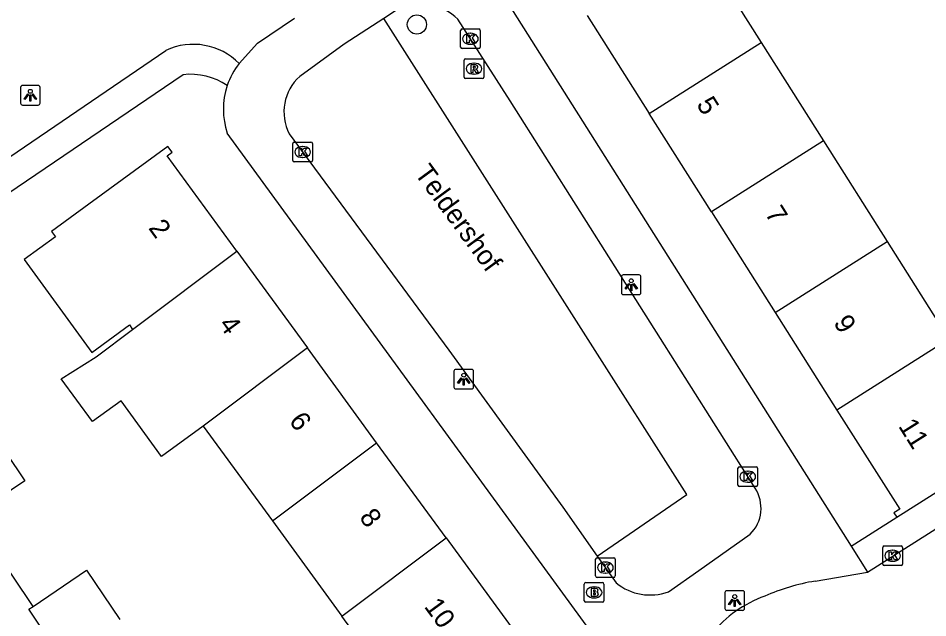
# Model space of a CAD drawing. Extents: x 157466 to 158888, y 383063 to 384677.
# Drawn here: x 158057.81 to 158104.15, y 383566.64 to 383597.18 of the extents above; entities that cross this region are included whole.
import ezdxf

# ---------------------------------------------------------------- set-up
doc = ezdxf.new("R2010")
doc.units = 0
for name, color, linetype in [('IMGEO_Boom', 7, 'Continuous'), ('IMGEO_Brandkraan', 7, 'Continuous'), ('IMGEO_Groenvoorziening', 7, 'Continuous'), ('IMGEO_Kolk', 7, 'Continuous'), ('IMGEO_Lichtpunt', 7, 'Continuous'), ('IMGEO_Openbare_ruimte_label', 7, 'Continuous'), ('IMGEO_Pand', 7, 'Continuous'), ('IMGEO_Pand_nummerreeks', 7, 'Continuous'), ('IMGEO_Rijbaan_lokaal_open', 7, 'Continuous'), ('IMGEO_Rioolput', 7, 'Continuous'), ('IMGEO_Voetpad_open', 7, 'Continuous')]:
    doc.layers.add(name, color=color, linetype=linetype)

msp = doc.modelspace()

# ---------------------------------------------------------------- linework, layer by layer
at = {"layer": 'IMGEO_Boom'}
msp.add_circle((158078.119, 383596.855), 0.489, dxfattribs=at)
at = {"layer": 'IMGEO_Brandkraan'}
for p, q in [((158086.649, 383567.512), (158086.649, 383568.364)), ((158086.724, 383568.438), (158087.576, 383568.438)), ((158087.65, 383568.364), (158087.65, 383567.512)), ((158087.137, 383568.218), (158087.162, 383568.218)), ((158087.576, 383567.438), (158086.724, 383567.438)), ((158087.16, 383567.658), (158087.135, 383567.658))]:
    msp.add_line(p, q, dxfattribs=at)
for points in [[(158086.649, 383567.512), (158086.649, 383568.364)], [(158086.724, 383568.438), (158087.576, 383568.438)], [(158087.65, 383568.364), (158087.65, 383567.512)], [(158086.997, 383568.138), (158086.997, 383567.738), (158087.21, 383567.738)], [(158087.228, 383568.138), (158086.997, 383568.138)], [(158087.176, 383568.057), (158087.122, 383568.057), (158087.122, 383567.981)], [(158087.122, 383567.981), (158087.175, 383567.981)], [(158087.184, 383567.905), (158087.122, 383567.905), (158087.122, 383567.824)], [(158087.576, 383567.438), (158086.724, 383567.438)], [(158087.122, 383567.824), (158087.184, 383567.824)]]:
    msp.add_lwpolyline(points, dxfattribs=at)
for centre, radius, start, end in [((158086.726, 383568.362), 0.0765, 91.552, 178.448), ((158086.726, 383568.362), 0.0765, 91.552, 178.448), ((158087.574, 383568.362), 0.0765, 1.552, 88.448), ((158087.574, 383568.362), 0.0765, 1.552, 88.448), ((158087.177, 383568.019), 0.0379, 267.8285, 90.9355), ((158087.185, 383567.864), 0.0404, 269.8759, 90.5077), ((158087.232, 383567.993), 0.145, 59.4692, 91.5367), ((158087.257, 383568.04), 0.0922, 285.5137, 58.1501), ((158087.262, 383567.848), 0.105, 301.3115, 78.989), ((158086.726, 383567.514), 0.0765, 181.552, 268.448), ((158086.726, 383567.514), 0.0765, 181.552, 268.448), ((158087.216, 383567.989), 0.251, 268.6676, 293.5347), ((158087.574, 383567.514), 0.0765, 271.552, 358.448), ((158087.574, 383567.514), 0.0765, 271.552, 358.448)]:
    msp.add_arc(centre, radius, start, end, dxfattribs=at)
for centre, major_axis, ratio, start_param, end_param in [((158087.136, 383567.938), (-0.387, 0.002), 0.722429, 4.712389, 7.853982), ((158087.161, 383567.938), (-0.39, 0.002), 0.717154, 1.570796, 4.712389)]:
    msp.add_ellipse(centre, major_axis=major_axis, ratio=ratio, start_param=start_param, end_param=end_param, dxfattribs=at)
at = {"layer": 'IMGEO_Groenvoorziening'}
msp.add_lwpolyline([(158087.311, 383569.79), (158091.867, 383572.916), (158076.432, 383597.167)], dxfattribs=at)
at = {"layer": 'IMGEO_Kolk'}
for p, q in [((158080.42, 383596.626), (158081.272, 383596.626)), ((158080.345, 383595.7), (158080.345, 383596.552)), ((158080.833, 383596.406), (158080.858, 383596.406)), ((158081.346, 383596.552), (158081.346, 383595.7)), ((158080.856, 383595.846), (158080.831, 383595.846)), ((158081.272, 383595.626), (158080.42, 383595.626)), ((158071.797, 383589.937), (158071.797, 383590.789)), ((158071.872, 383590.863), (158072.724, 383590.863)), ((158072.285, 383590.643), (158072.31, 383590.643)), ((158072.798, 383590.789), (158072.798, 383589.937)), ((158072.724, 383589.863), (158071.872, 383589.863)), ((158072.308, 383590.083), (158072.283, 383590.083)), ((158094.478, 383573.403), (158094.478, 383574.255)), ((158094.553, 383574.329), (158095.405, 383574.329)), ((158094.966, 383574.109), (158094.991, 383574.109)), ((158095.479, 383574.255), (158095.479, 383573.403)), ((158094.989, 383573.549), (158094.964, 383573.549)), ((158095.405, 383573.329), (158094.553, 383573.329)), ((158101.86, 383569.376), (158101.86, 383570.228)), ((158101.935, 383570.302), (158102.787, 383570.302)), ((158102.861, 383570.228), (158102.861, 383569.376)), ((158102.348, 383570.082), (158102.373, 383570.082)), ((158087.224, 383568.773), (158087.224, 383569.625)), ((158087.299, 383569.699), (158088.151, 383569.699)), ((158087.712, 383569.479), (158087.737, 383569.479)), ((158088.225, 383569.625), (158088.225, 383568.773)), ((158102.787, 383569.302), (158101.935, 383569.302)), ((158102.371, 383569.522), (158102.346, 383569.522)), ((158087.735, 383568.919), (158087.71, 383568.919)), ((158088.151, 383568.699), (158087.299, 383568.699))]:
    msp.add_line(p, q, dxfattribs=at)
for points in [[(158080.42, 383596.626), (158081.272, 383596.626)], [(158080.345, 383595.7), (158080.345, 383596.552)], [(158080.666, 383596.326), (158080.789, 383596.326), (158080.789, 383596.175), (158080.919, 383596.326), (158081.083, 383596.326), (158080.937, 383596.175), (158081.09, 383595.926), (158080.938, 383595.926), (158080.853, 383596.09), (158080.789, 383596.023), (158080.789, 383595.926), (158080.666, 383595.926), (158080.666, 383596.326)], [(158081.346, 383596.552), (158081.346, 383595.7)], [(158081.272, 383595.626), (158080.42, 383595.626)], [(158071.797, 383589.937), (158071.797, 383590.789)], [(158071.872, 383590.863), (158072.724, 383590.863)], [(158072.798, 383590.789), (158072.798, 383589.937)], [(158072.118, 383590.563), (158072.241, 383590.563), (158072.241, 383590.412), (158072.371, 383590.563), (158072.535, 383590.563), (158072.389, 383590.412), (158072.542, 383590.163), (158072.39, 383590.163), (158072.305, 383590.327), (158072.241, 383590.26), (158072.241, 383590.163), (158072.118, 383590.163), (158072.118, 383590.563)], [(158072.724, 383589.863), (158071.872, 383589.863)], [(158094.478, 383573.403), (158094.478, 383574.255)], [(158094.553, 383574.329), (158095.405, 383574.329)], [(158094.799, 383574.029), (158094.922, 383574.029), (158094.922, 383573.878), (158095.052, 383574.029), (158095.216, 383574.029), (158095.07, 383573.878), (158095.223, 383573.629), (158095.071, 383573.629), (158094.986, 383573.793), (158094.922, 383573.726), (158094.922, 383573.629), (158094.799, 383573.629), (158094.799, 383574.029)], [(158095.479, 383574.255), (158095.479, 383573.403)], [(158095.405, 383573.329), (158094.553, 383573.329)], [(158101.86, 383569.376), (158101.86, 383570.228)], [(158101.935, 383570.302), (158102.787, 383570.302)], [(158102.861, 383570.228), (158102.861, 383569.376)], [(158102.181, 383570.002), (158102.304, 383570.002), (158102.304, 383569.851), (158102.434, 383570.002), (158102.598, 383570.002), (158102.452, 383569.851), (158102.605, 383569.602), (158102.453, 383569.602), (158102.368, 383569.766), (158102.304, 383569.699), (158102.304, 383569.602), (158102.181, 383569.602), (158102.181, 383570.002)], [(158087.224, 383568.773), (158087.224, 383569.625)], [(158087.299, 383569.699), (158088.151, 383569.699)], [(158087.545, 383569.399), (158087.668, 383569.399), (158087.668, 383569.248), (158087.798, 383569.399), (158087.962, 383569.399), (158087.816, 383569.248), (158087.969, 383568.999), (158087.817, 383568.999), (158087.732, 383569.163), (158087.668, 383569.096), (158087.668, 383568.999), (158087.545, 383568.999), (158087.545, 383569.399)], [(158088.225, 383569.625), (158088.225, 383568.773)], [(158102.787, 383569.302), (158101.935, 383569.302)], [(158088.151, 383568.699), (158087.299, 383568.699)]]:
    msp.add_lwpolyline(points, dxfattribs=at)
for centre, start, end in [((158080.422, 383596.55), 91.552, 178.448), ((158080.422, 383596.55), 91.552, 178.448), ((158081.27, 383596.55), 1.552, 88.448), ((158081.27, 383596.55), 1.552, 88.448), ((158080.422, 383595.702), 181.552, 268.448), ((158080.422, 383595.702), 181.552, 268.448), ((158081.27, 383595.702), 271.552, 358.448), ((158081.27, 383595.702), 271.552, 358.448), ((158071.874, 383590.787), 91.552, 178.448), ((158071.874, 383590.787), 91.552, 178.448), ((158072.722, 383590.787), 1.552, 88.448), ((158072.722, 383590.787), 1.552, 88.448), ((158071.874, 383589.939), 181.552, 268.448), ((158071.874, 383589.939), 181.552, 268.448), ((158072.722, 383589.939), 271.552, 358.448), ((158072.722, 383589.939), 271.552, 358.448), ((158094.555, 383574.253), 91.552, 178.448), ((158094.555, 383574.253), 91.552, 178.448), ((158095.403, 383574.253), 1.552, 88.448), ((158095.403, 383574.253), 1.552, 88.448), ((158094.555, 383573.405), 181.552, 268.448), ((158094.555, 383573.405), 181.552, 268.448), ((158095.403, 383573.405), 271.552, 358.448), ((158095.403, 383573.405), 271.552, 358.448), ((158101.937, 383570.226), 91.552, 178.448), ((158101.937, 383570.226), 91.552, 178.448), ((158102.785, 383570.226), 1.552, 88.448), ((158102.785, 383570.226), 1.552, 88.448), ((158087.301, 383569.623), 91.552, 178.448), ((158087.301, 383569.623), 91.552, 178.448), ((158088.149, 383569.623), 1.552, 88.448), ((158088.149, 383569.623), 1.552, 88.448), ((158101.937, 383569.378), 181.552, 268.448), ((158101.937, 383569.378), 181.552, 268.448), ((158102.785, 383569.378), 271.552, 358.448), ((158102.785, 383569.378), 271.552, 358.448), ((158087.301, 383568.775), 181.552, 268.448), ((158087.301, 383568.775), 181.552, 268.448), ((158088.149, 383568.775), 271.552, 358.448), ((158088.149, 383568.775), 271.552, 358.448)]:
    msp.add_arc(centre, 0.0765, start, end, dxfattribs=at)
for centre, major_axis, ratio, start_param, end_param in [((158080.832, 383596.126), (-0.387, 0.002), 0.722429, 4.712389, 7.853982), ((158080.857, 383596.126), (-0.39, 0.002), 0.717154, 1.570796, 4.712389), ((158072.284, 383590.363), (-0.387, 0.002), 0.722429, 4.712389, 7.853982), ((158072.309, 383590.363), (-0.39, 0.002), 0.717154, 1.570796, 4.712389), ((158094.965, 383573.829), (-0.387, 0.002), 0.722429, 4.712389, 7.853982), ((158094.99, 383573.829), (-0.39, 0.002), 0.717154, 1.570796, 4.712389), ((158102.347, 383569.802), (-0.387, 0.002), 0.722429, 4.712389, 7.853982), ((158102.372, 383569.802), (-0.39, 0.002), 0.717154, 1.570796, 4.712389), ((158087.711, 383569.199), (-0.387, 0.002), 0.722429, 4.712389, 7.853982), ((158087.736, 383569.199), (-0.39, 0.002), 0.717154, 1.570796, 4.712389)]:
    msp.add_ellipse(centre, major_axis=major_axis, ratio=ratio, start_param=start_param, end_param=end_param, dxfattribs=at)
at = {"layer": 'IMGEO_Lichtpunt'}
for p, q in [((158057.926, 383593.654), (158057.926, 383592.847)), ((158057.926, 383593.654), (158057.926, 383592.847)), ((158058.828, 383593.749), (158058.02, 383593.749)), ((158058.828, 383593.749), (158058.02, 383593.749)), ((158058.922, 383592.847), (158058.922, 383593.654)), ((158058.922, 383592.847), (158058.922, 383593.654)), ((158058.02, 383592.753), (158058.828, 383592.753)), ((158058.02, 383592.753), (158058.828, 383592.753)), ((158088.541, 383584.006), (158088.541, 383583.199)), ((158088.541, 383584.006), (158088.541, 383583.199)), ((158089.443, 383584.101), (158088.635, 383584.101)), ((158089.443, 383584.101), (158088.635, 383584.101)), ((158089.537, 383583.199), (158089.537, 383584.006)), ((158089.537, 383583.199), (158089.537, 383584.006)), ((158088.635, 383583.105), (158089.443, 383583.105)), ((158088.635, 383583.105), (158089.443, 383583.105)), ((158080.009, 383579.199), (158080.009, 383578.392)), ((158080.009, 383579.199), (158080.009, 383578.392)), ((158080.911, 383579.294), (158080.103, 383579.294)), ((158080.911, 383579.294), (158080.103, 383579.294)), ((158081.005, 383578.392), (158081.005, 383579.199)), ((158081.005, 383578.392), (158081.005, 383579.199)), ((158080.103, 383578.298), (158080.911, 383578.298)), ((158080.103, 383578.298), (158080.911, 383578.298)), ((158093.814, 383567.925), (158093.814, 383567.118)), ((158093.814, 383567.925), (158093.814, 383567.118)), ((158094.716, 383568.02), (158093.908, 383568.02)), ((158094.716, 383568.02), (158093.908, 383568.02)), ((158094.81, 383567.118), (158094.81, 383567.925)), ((158094.81, 383567.118), (158094.81, 383567.925)), ((158093.908, 383567.024), (158094.716, 383567.024)), ((158093.908, 383567.024), (158094.716, 383567.024))]:
    msp.add_line(p, q, dxfattribs=at)
for points in [[(158058.3, 383593.318), (158058.339, 383593.29), (158058.151, 383593.028), (158058.113, 383593.055), (158058.3, 383593.318)], [(158058.402, 383593.27), (158058.449, 383593.27), (158058.449, 383592.948), (158058.402, 383592.948), (158058.402, 383593.27)], [(158058.512, 383593.29), (158058.55, 383593.317), (158058.737, 383593.055), (158058.698, 383593.027), (158058.512, 383593.29)], [(158088.915, 383583.67), (158088.954, 383583.642), (158088.766, 383583.38), (158088.728, 383583.407), (158088.915, 383583.67)], [(158089.127, 383583.642), (158089.165, 383583.669), (158089.352, 383583.407), (158089.313, 383583.379), (158089.127, 383583.642)], [(158089.017, 383583.622), (158089.064, 383583.622), (158089.064, 383583.3), (158089.017, 383583.3), (158089.017, 383583.622)], [(158080.383, 383578.863), (158080.422, 383578.835), (158080.234, 383578.573), (158080.196, 383578.6), (158080.383, 383578.863)], [(158080.485, 383578.815), (158080.532, 383578.815), (158080.532, 383578.493), (158080.485, 383578.493), (158080.485, 383578.815)], [(158080.595, 383578.835), (158080.633, 383578.862), (158080.82, 383578.6), (158080.781, 383578.572), (158080.595, 383578.835)], [(158094.188, 383567.589), (158094.227, 383567.561), (158094.039, 383567.299), (158094.001, 383567.326), (158094.188, 383567.589)], [(158094.29, 383567.541), (158094.337, 383567.541), (158094.337, 383567.219), (158094.29, 383567.219), (158094.29, 383567.541)], [(158094.4, 383567.561), (158094.438, 383567.588), (158094.625, 383567.326), (158094.586, 383567.298), (158094.4, 383567.561)]]:
    msp.add_lwpolyline(points, dxfattribs=at)
for centre in [(158058.425, 383593.452), (158089.04, 383583.804), (158080.508, 383578.997), (158094.313, 383567.723)]:
    msp.add_circle(centre, 0.0994, dxfattribs=at)
for centre, start, end in [((158058.02, 383593.654), 90, 180), ((158058.02, 383593.654), 90, 180), ((158058.828, 383593.654), 0, 90), ((158058.828, 383593.654), 0, 90), ((158058.02, 383592.847), 180, 270), ((158058.02, 383592.847), 180, 270), ((158058.828, 383592.847), 270, 0), ((158058.828, 383592.847), 270, 360), ((158088.635, 383584.006), 90, 180), ((158088.635, 383584.006), 90, 180), ((158089.443, 383584.006), 0, 90), ((158089.443, 383584.006), 0, 90), ((158088.635, 383583.199), 180, 270), ((158088.635, 383583.199), 180, 270), ((158089.443, 383583.199), 270, 0), ((158089.443, 383583.199), 270, 360), ((158080.103, 383579.199), 90, 180), ((158080.103, 383579.199), 90, 180), ((158080.911, 383579.199), 0, 90), ((158080.911, 383579.199), 0, 90), ((158080.103, 383578.392), 180, 270), ((158080.103, 383578.392), 180, 270), ((158080.911, 383578.392), 270, 0), ((158080.911, 383578.392), 270, 360), ((158093.908, 383567.925), 90, 180), ((158093.908, 383567.925), 90, 180), ((158094.716, 383567.925), 0, 90), ((158094.716, 383567.925), 0, 90), ((158093.908, 383567.118), 180, 270), ((158093.908, 383567.118), 180, 270), ((158094.716, 383567.118), 270, 0), ((158094.716, 383567.118), 270, 360)]:
    msp.add_arc(centre, 0.0946, start, end, dxfattribs=at)
at = {"layer": 'IMGEO_Pand'}
for points in [[(158092.495, 383600.924), (158095.657, 383595.935)], [(158086.789, 383597.305), (158089.952, 383592.315)], [(158089.952, 383592.315), (158095.657, 383595.935)], [(158095.657, 383595.935), (158098.833, 383590.926)], [(158093.127, 383587.307), (158089.952, 383592.315)], [(158068.947, 383585.314), (158065.402, 383590.169), (158065.652, 383590.352), (158065.435, 383590.649), (158061.397, 383587.701), (158059.506, 383586.32), (158059.705, 383586.047), (158058.105, 383584.881), (158061.55, 383580.153), (158063.474, 383581.555), (158063.637, 383581.332)], [(158098.833, 383590.926), (158093.127, 383587.307)], [(158098.833, 383590.926), (158102.075, 383585.81)], [(158093.127, 383587.307), (158096.369, 383582.191)], [(158096.369, 383582.191), (158102.075, 383585.81)], [(158102.075, 383585.81), (158105.228, 383580.836)], [(158063.637, 383581.332), (158068.947, 383585.314)], [(158068.947, 383585.314), (158072.54, 383580.392)], [(158096.369, 383582.191), (158099.522, 383577.217)], [(158067.23, 383576.41), (158065.113, 383574.857), (158063.046, 383577.688), (158061.599, 383576.631), (158060.002, 383578.819), (158061.775, 383579.936), (158063.637, 383581.332)], [(158105.228, 383580.836), (158099.522, 383577.217)], [(158072.54, 383580.392), (158067.23, 383576.41)], [(158076.069, 383575.559), (158072.54, 383580.392)], [(158099.522, 383577.217), (158102.719, 383572.174), (158102.423, 383571.987), (158102.566, 383571.761)], [(158102.566, 383571.761), (158106.79, 383574.438), (158108.848, 383575.743), (158110.56, 383576.829)], [(158056.227, 383576.451), (158058.137, 383573.619), (158055.464, 383571.816)], [(158067.23, 383576.41), (158070.759, 383571.577)], [(158070.759, 383571.577), (158076.069, 383575.559)], [(158079.606, 383570.714), (158076.069, 383575.559)], [(158070.759, 383571.577), (158074.296, 383566.732)], [(158074.296, 383566.732), (158079.606, 383570.714)], [(158079.606, 383570.714), (158083.104, 383565.922)], [(158058.564, 383567.221), (158061.292, 383569.062), (158062.983, 383566.557)], [(158060.037, 383564.577), (158058.35, 383567.077), (158058.564, 383567.221)], [(158077.795, 383561.94), (158074.296, 383566.732)]]:
    msp.add_lwpolyline(points, dxfattribs=at)
at = {"layer": 'IMGEO_Rijbaan_lokaal_open'}
for points in [[(158082.083, 383599.002), (158100.243, 383570.288)], [(158077.227, 383597.687), (158076.432, 383597.167)], [(158069.065, 383594.868), (158069.99, 383595.903), (158071.886, 383597.183)], [(158076.432, 383597.167), (158074.419, 383595.851), (158072.152, 383594.213)], [(158095.348, 383573.246), (158082.874, 383592.971), (158080.205, 383597.122)], [(158089.222, 383562.881), (158068.458, 383591.321)], [(158071.618, 383591.287), (158079.743, 383580.27), (158085.554, 383572.285), (158087.311, 383569.79)], [(158101.077, 383568.969), (158104.874, 383571.383)], [(158090.932, 383567.969), (158092.488, 383569.052), (158095.097, 383570.898)], [(158100.243, 383570.288), (158101.077, 383568.969)], [(158087.311, 383569.79), (158088.275, 383568.422)], [(158098.405, 383568.512), (158101.077, 383568.969)]]:
    msp.add_lwpolyline(points, dxfattribs=at)
for centre, radius, start, end in [((158078.297, 383595.198), 2.709, 45.2439, 113.2706), ((158071.834, 383592.634), 3.558, 141.0992, 161.8511), ((158073.771, 383592.406), 2.426, 131.8554, 207.4591), ((158072.125, 383592.539), 3.864, 161.8621, 198.3746), ((158093.794, 383572.225), 1.86, 314.4851, 33.3115), ((158090, 383570.522), 2.718, 230.5986, 290.0504), ((158100.215, 383557.781), 10.883, 99.5714, 113.6958), ((158097.895, 383562.001), 6.101, 109.6718, 141.0074)]:
    msp.add_arc(centre, radius, start, end, dxfattribs=at)
at = {"layer": 'IMGEO_Rioolput'}
for p, q in [((158080.526, 383594.179), (158080.526, 383595.031)), ((158080.601, 383595.105), (158081.453, 383595.105)), ((158081.014, 383594.885), (158081.039, 383594.885)), ((158081.527, 383595.031), (158081.527, 383594.179)), ((158081.037, 383594.325), (158081.012, 383594.325)), ((158081.453, 383594.105), (158080.601, 383594.105))]:
    msp.add_line(p, q, dxfattribs=at)
for points in [[(158080.526, 383594.179), (158080.526, 383595.031)], [(158080.601, 383595.105), (158081.453, 383595.105)], [(158081.115, 383594.803), (158080.863, 383594.805), (158080.863, 383594.405)], [(158081.527, 383595.031), (158081.527, 383594.179)], [(158080.863, 383594.405), (158080.987, 383594.405), (158080.987, 383594.567), (158080.998, 383594.567)], [(158081.041, 383594.724), (158080.987, 383594.724), (158080.987, 383594.643)], [(158080.987, 383594.643), (158081.039, 383594.643)], [(158081.045, 383594.538), (158081.116, 383594.405), (158081.256, 383594.405), (158081.191, 383594.531)], [(158081.453, 383594.105), (158080.601, 383594.105)]]:
    msp.add_lwpolyline(points, dxfattribs=at)
for centre, radius, start, end in [((158080.603, 383595.029), 0.0765, 91.552, 178.448), ((158080.603, 383595.029), 0.0765, 91.552, 178.448), ((158081.114, 383594.693), 0.109, 350.3612, 89.416), ((158081.451, 383595.029), 0.0765, 1.552, 88.448), ((158081.451, 383595.029), 0.0765, 1.552, 88.448), ((158080.997, 383594.514), 0.0533, 26.0293, 88.6989), ((158081.023, 383594.832), 0.19, 274.7715, 282.9687), ((158081.047, 383594.628), 0.0964, 77.0061, 93.1865), ((158081.061, 383594.685), 0.0378, 276.6634, 79.6772), ((158081.112, 383594.693), 0.112, 277.5842, 350.9817), ((158081.096, 383594.478), 0.108, 29.5134, 73.7905), ((158080.603, 383594.181), 0.0765, 181.552, 268.448), ((158080.603, 383594.181), 0.0765, 181.552, 268.448), ((158081.451, 383594.181), 0.0765, 271.552, 358.448), ((158081.451, 383594.181), 0.0765, 271.552, 358.448)]:
    msp.add_arc(centre, radius, start, end, dxfattribs=at)
for centre, major_axis, ratio, start_param, end_param in [((158081.013, 383594.605), (-0.387, 0.002), 0.722429, 4.712389, 7.853982), ((158081.038, 383594.605), (-0.39, 0.002), 0.717154, 1.570796, 4.712389)]:
    msp.add_ellipse(centre, major_axis=major_axis, ratio=ratio, start_param=start_param, end_param=end_param, dxfattribs=at)
at = {"layer": 'IMGEO_Voetpad_open'}
for points in [[(158052.832, 383587.022), (158065.325, 383595.538)], [(158066.203, 383594.297), (158048.37, 383582.204)], [(158058.564, 383567.221), (158055.479, 383571.794), (158055.464, 383571.816)], [(158100.243, 383570.288), (158102.566, 383571.761)]]:
    msp.add_lwpolyline(points, dxfattribs=at)
for centre, radius, start, end in [((158066.717, 383592.535), 3.31, 44.8188, 114.8683), ((158066.586, 383591.011), 3.308, 55.6416, 96.6457)]:
    msp.add_arc(centre, radius, start, end, dxfattribs=at)

# ---------------------------------------------------------------- texts
at = {"layer": 'IMGEO_Openbare_ruimte_label'}
msp.add_text('Teldershof', height=1, rotation=306.2508, dxfattribs=at).set_placement((158077.965, 383589.27))
at = {"layer": 'IMGEO_Pand_nummerreeks'}
for s, rotation, p in [('5', 302.1374, (158092.335, 383592.785)), ('7', 302.1374, (158095.826, 383587.228)), ('2', 306.0884, (158064.411, 383586.486)), ('4', 306.0884, (158067.99, 383581.575)), ('9', 302.1374, (158099.317, 383581.671)), ('6', 306.0884, (158071.569, 383576.666)), ('11', 302.1374, (158102.623, 383576.406)), ('8', 306.0884, (158075.15, 383571.752)), ('10', 306.0884, (158078.457, 383567.215))]:
    msp.add_text(s, height=1, rotation=rotation, dxfattribs=at).set_placement(p)

doc.saveas('drawing.dxf')
